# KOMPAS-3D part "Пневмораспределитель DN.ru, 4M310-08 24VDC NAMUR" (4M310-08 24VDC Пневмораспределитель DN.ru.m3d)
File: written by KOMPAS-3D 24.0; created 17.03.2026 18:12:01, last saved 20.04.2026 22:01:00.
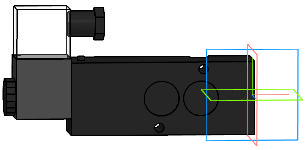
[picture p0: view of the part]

Document properties: Автор: R2D2; Полное имя файла: E:\Работа\Зайцев\Аксессуары для пневмоприводов\Пневмораспределители DN.ru\4М310-08 NAMUR Пневмораспределитель DN.RU\4М310-08 24VDC NAMUR Пневмораспределитель DN.RU\исходные материалы\4M310-08 24VDC Пневмораспределитель DN.ru.m3d

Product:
- Body: Тело 1  | qty 1
    Масса: 1.13605
- Part/product: Пневмораспределитель DN.ru  | designation 4M310-08 24VDC NAMUR
    Масса: 0.35
    Раздел спецификации: Прочие изделия
    Примечание: D290-00330

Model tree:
1. Эскиз:1
2. Элемент выдавливания:1
     Расстояние 2 = 100
3. Эскиз:2  (with: Грань.Элемент выдавливания:1)
4. Элемент выдавливания:2
     Расстояние 2 = 1
5. Эскиз:3  (with: Грань.Элемент выдавливания:1)
6. Элемент выдавливания:3
     Расстояние 2 = 27
7. Эскиз:4  (with: Грань.Элемент выдавливания:1, Ребро.Элемент выдавливания:1)
8. Элемент выдавливания:4
     Расстояние 1 = 30
9. Эскиз:5  (with: Грань.Элемент выдавливания:4, Ребро.Элемент выдавливания:4)
10. Элемент выдавливания:5
     Расстояние 1 = 27
11. Эскиз:6  (with: Грань.Элемент выдавливания:4)
12. Элемент выдавливания:6
     Расстояние 1 = 5
13. Эскиз:7  (with: Грань.Элемент выдавливания:5)
14. Элемент выдавливания:7
     Расстояние 1 = 14
15. Эскиз:8  (with: Грань.Элемент выдавливания:7, Ребро.Элемент выдавливания:7)
16. Элемент выдавливания:8
     Расстояние 1 = 5
17. Эскиз:9  (with: Грань.Элемент выдавливания:1)
18. Элемент выдавливания:9
     Расстояние 1 = 2
19. Эскиз:10  (with: Грань.Элемент выдавливания:1)
20. Элемент выдавливания:10
     Расстояние 2 = 5
21. Эскиз:11  (with: Грань.Элемент выдавливания:1, Ребро.Элемент выдавливания:3)
22. Элемент выдавливания:11
     Расстояние 2 = 5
